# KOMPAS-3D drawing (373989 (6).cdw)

Referenced files in C:\Documents and Settings\оля\Мои документы\Чертежи схемы установок\: На внутреннюю цилиндрическую поверхность.frw, На плоскости.frw, Направление усилия.frw, На наружнюю цилиндрическую поверхность.frw
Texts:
  Текст на чертеже
  Размерные надписи
  Шероховатость
  Линия-выноска #1
  Линия-выноска #2
  Линия-выноска #3
  Отклонения формы и база
  Заголовок таблицы
  Ячейка таблицы
  Стрелка вида
  Обозначение изменения
  Фигурная скобка
  Номер узла
  Марка координационной оси
  VRCB
  Выносная надпись
  Обозначение узла
  Марка/позиционное обозначение с линией-выноской
  Марка/позиционное обозначение на линии
  Марка/позиционное обозначение без линии-выноски
  Упор
  Оля
  Изм. Лист № докум      Подпись      Дата
  Дублик
  Взамен
  Подпись
  Изм.
  Лист
  № докумен.
  Дата
  ТС-51.60240
  СК-4.54.60640
  Операция 35. Зубопритирочная
  Rz20
  Операция 40. Шлифовальная
  Ra1.25
Dimensions and other numbers on the sheet: 7; 4; 108; 72; 1:1; 0; 1; 2; 3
